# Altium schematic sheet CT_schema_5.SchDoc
size 298 x 177 mm
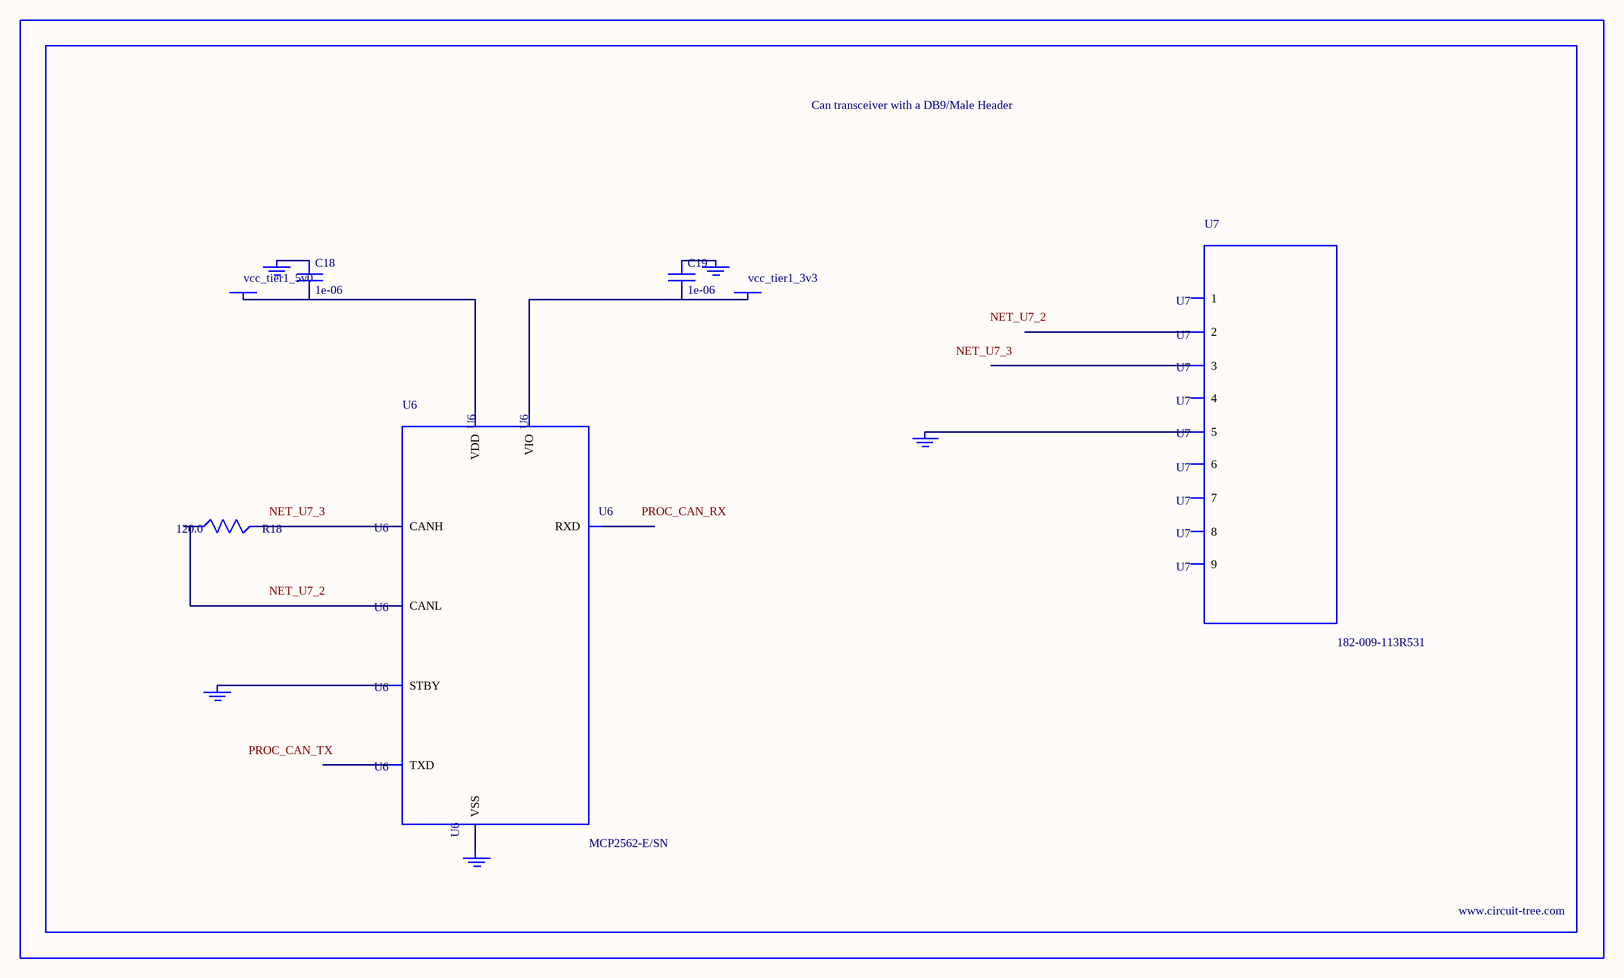
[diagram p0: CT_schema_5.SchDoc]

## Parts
BORDER4  (no value)
C18  1e-06  [C0603]
C19  1e-06  [C0603]
GND_INSTANCE_4_0  (no value)
GND_INSTANCE_4_1  (no value)
GND_INSTANCE_4_2  (no value)
GND_INSTANCE_4_3  (no value)
GND_INSTANCE_4_4  (no value)
POWER_INSTANCE_4_0  vcc_tier1_5v0
POWER_INSTANCE_4_1  vcc_tier1_3v3
R18  120.0  [R0603]
U6  MCP2562-E/SN  [SOIC-8]
U7  182-009-113R531  [182-009-MALE]

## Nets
NetC18_1: C18.1 GND_INSTANCE_4_0.0(GND)
NetC18_2: C18.2 POWER_INSTANCE_4_0.0(PWR) U6.3(VDD)
NetC19_1: C19.1 GND_INSTANCE_4_1.0(GND)
NetC19_2: C19.2 POWER_INSTANCE_4_1.0(PWR) U6.5(VIO)
NetGND_INSTANCE_4_2_0: GND_INSTANCE_4_2.0(GND) U6.8(STBY)
NetGND_INSTANCE_4_3_0: GND_INSTANCE_4_3.0(GND) U6.2(VSS)
NetGND_INSTANCE_4_4_0: GND_INSTANCE_4_4.0(GND) U7.5
NetR18_1: R18.1 U6.6(CANL)
NetR18_2: R18.2 U6.7(CANH)

Not connected (* = marked no-connect by the designer): U6 1(TXD) 4(RXD); U7 1 2 3 4 6 7 8 9

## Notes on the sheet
- Labels drawn without touching a wire or pin: NET_U7_2, NET_U7_3, PROC_CAN_RX, PROC_CAN_TX

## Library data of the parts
BORDER4 = BORDER_PAGE4
C18 C19 = C0603C105K3RACTU
GND_INSTANCE_4_0-GND_INSTANCE_4_4 = GND
POWER_INSTANCE_4_0 POWER_INSTANCE_4_1 = PWR
R18 = RC0603JR-07120RL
